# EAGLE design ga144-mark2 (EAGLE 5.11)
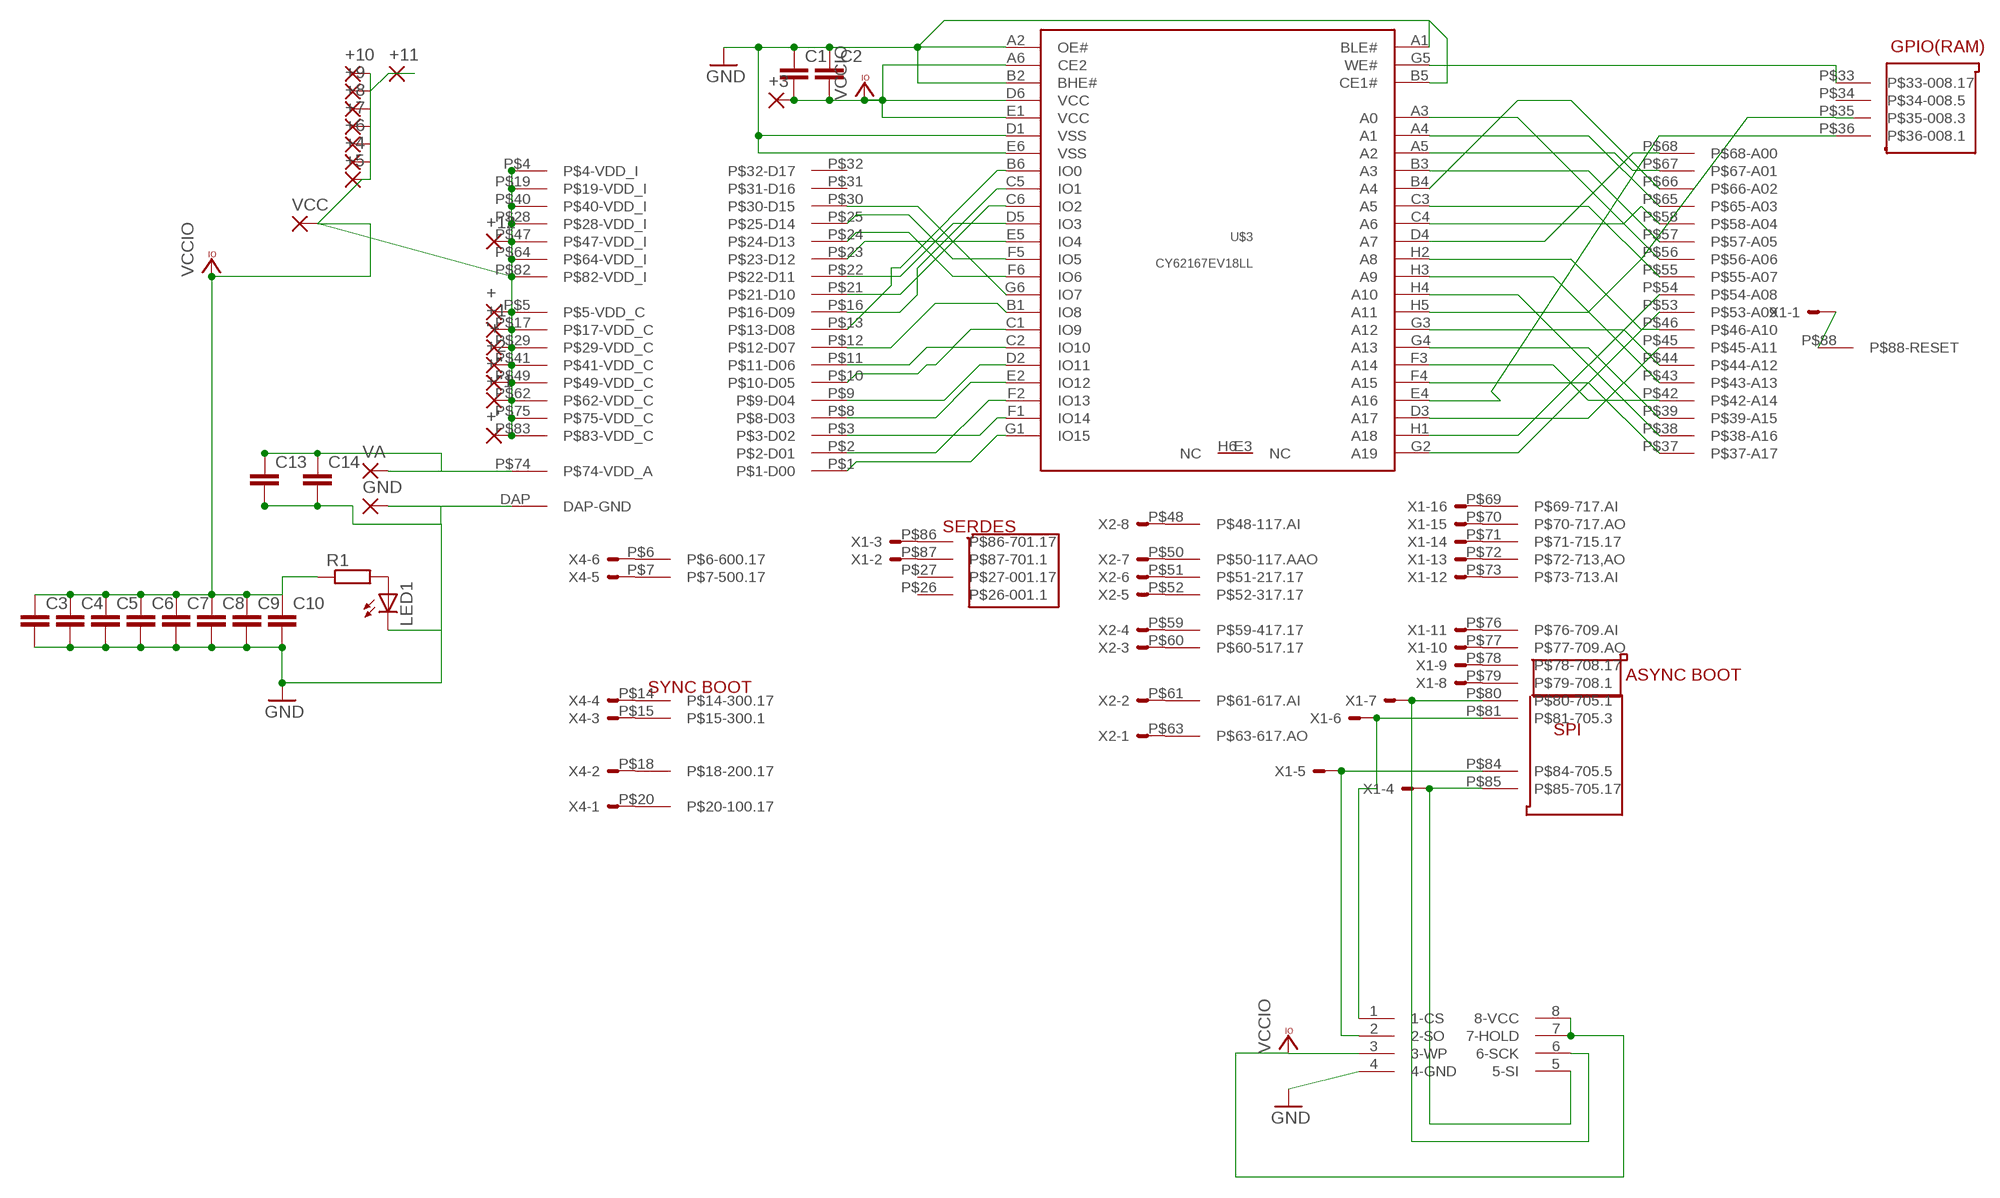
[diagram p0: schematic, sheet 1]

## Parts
'+  1,6/0,8  [1,6/0,8]
+  1,6/0,8  [1,6/0,8]
+1  1,6/0,8  [1,6/0,8]
+2  1,6/0,8  [1,6/0,8]
+3  1,6/0,8  [1,6/0,8]
+4  1,6/0,8  [1,6/0,8]
+5  1,6/0,8  [1,6/0,8]
+6  1,6/0,8  [1,6/0,8]
+7  1,6/0,8  [1,6/0,8]
+8  1,6/0,8  [1,6/0,8]
+9  1,6/0,8  [1,6/0,8]
+10  1,6/0,8  [1,6/0,8]
+11  1,6/0,8  [1,6/0,8]
+12  1,6/0,8  [1,6/0,8]
+"  1,6/0,8  [1,6/0,8]
+"1  1,6/0,8  [1,6/0,8]
+'  1,6/0,8  [1,6/0,8]
C1  C-EUC0805  [C0805]
C2  C-EUC0805  [C0805]
C3  C-EUC0805  [C0805]
C4  C-EUC0805  [C0805]
C5  C-EUC0805  [C0805]
C6  C-EUC0805  [C0805]
C7  C-EUC0805  [C0805]
C8  C-EUC0805  [C0805]
C9  C-EUC0805  [C0805]
C10  C-EUC0805  [C0805]
C13  C-EUC0805  [C0805]
C14  C-EUC0805  [C0805]
GND  2,54/1,0  [2,54/1,0]
LED1  LEDCHIPLED_0805  [CHIPLED_0805]
R1  R-EU_R0805  [R0805]
U$1  GA144A12  [QFN-88]
U$2  AT25DF081-SPI-FLASH  [SOIC8]
U$3  CY62167EV18LL  [BGA48]
VA  WIREPAD2,15/1,0  [2,15/1,0]
VCC  2,54/1,0  [2,54/1,0]
X1  KK-156-16  [KK-156-16]
X2  KK-156-8  [KK-156-8]
X4  KK-156-6  [KK-156-6]

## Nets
GND: C1.1 C2.1 C3.2 C4.2 C5.2 C6.2 C7.2 C8.2 C9.2 C10.2 C13.2 C14.2 GND.1(P) LED1.C U$1.DAP(DAP-GND) U$2.4(4-GND) U$3.A1(BLE#) U$3.A2(OE#) U$3.B2(BHE#) U$3.B5(CE1#) U$3.D1(VSS) U$3.E6(VSS)
N$1: U$1.P$88(P$88-RESET) X1.1
N$2: U$1.P$87(P$87-701.1) X1.2
N$3: C13.1 C14.1 U$1.P$74(P$74-VDD_A) VA.1(P)
N$4: U$1.P$86(P$86-701.17) X1.3
N$5: U$1.P$81(P$81-705.3) U$2.1(1-CS) X1.6
N$6: U$1.P$43(P$43-A13) U$3.H3(A9)
N$7: U$1.P$44(P$44-A12) U$3.G3(A12)
N$8: U$1.P$46(P$46-A10) U$3.H2(A8)
N$9: U$1.P$84(P$84-705.5) U$2.2(2-SO) X1.5
N$10: U$1.P$85(P$85-705.17) U$2.5(5-SI) X1.4
N$11: U$1.P$80(P$80-705.1) U$2.6(6-SCK) X1.7
N$12: U$1.P$79(P$79-708.1) X1.8
N$13: U$1.P$78(P$78-708.17) X1.9
N$14: U$1.P$77(P$77-709.AO) X1.10
N$15: U$1.P$76(P$76-709.AI) X1.11
N$16: U$1.P$73(P$73-713.AI) X1.12
N$17: U$1.P$72(P$72-713,AO) X1.13
N$18: U$1.P$71(P$71-715.17) X1.14
N$19: U$1.P$70(P$70-717.AO) X1.15
N$20: U$1.P$69(P$69-717.AI) X1.16
N$21: U$1.P$63(P$63-617.AO) X2.1
N$22: U$1.P$61(P$61-617.AI) X2.2
N$23: U$1.P$60(P$60-517.17) X2.3
N$24: U$1.P$59(P$59-417.17) X2.4
N$25: U$1.P$52(P$52-317.17) X2.5
N$26: U$1.P$51(P$51-217.17) X2.6
N$27: U$1.P$50(P$50-117.AAO) X2.7
N$28: U$1.P$48(P$48-117.AI) X2.8
N$29: U$1.P$36(P$36-008.1) U$3.E4(A16)
N$30: U$1.P$35(P$35-008.3) U$3.H5(A11)
N$31: U$1.P$55(P$55-A07) U$3.C3(A5)
N$32: U$1.P$57(P$57-A05) U$3.B3(A3)
N$33: U$1.P$56(P$56-A06) U$3.A3(A0)
N$34: U$1.P$58(P$58-A04) U$3.C4(A6)
N$35: U$1.P$6(P$6-600.17) X4.6
N$36: U$1.P$7(P$7-500.17) X4.5
N$37: U$1.P$14(P$14-300.17) X4.4
N$38: U$1.P$15(P$15-300.1) X4.3
N$39: U$1.P$18(P$18-200.17) X4.2
N$40: U$1.P$20(P$20-100.17) X4.1
N$41: U$1.P$53(P$53-A09) U$3.G2(A19)
N$42: U$1.P$54(P$54-A08) U$3.H1(A18)
N$43: U$1.P$39(P$39-A15) U$3.G4(A13)
N$44: U$1.P$45(P$45-A11) U$3.D3(A17)
N$45: U$1.P$38(P$38-A16) U$3.H4(A10)
N$46: U$1.P$42(P$42-A14) U$3.F3(A14)
N$47: U$1.P$65(P$65-A03) U$3.A4(A1)
N$48: U$1.P$37(P$37-A17) U$3.F4(A15)
N$49: U$1.P$66(P$66-A02) U$3.B4(A4)
N$50: U$1.P$67(P$67-A01) U$3.A5(A2)
N$51: U$1.P$68(P$68-A00) U$3.D4(A7)
N$52: U$1.P$30(P$30-D15) U$3.G6(IO7)
N$54: U$1.P$23(P$23-D12) U$3.E5(IO4)
N$55: U$1.P$25(P$25-D14) U$3.F5(IO5)
N$56: U$1.P$12(P$12-D07) U$3.B1(IO8)
N$57: U$1.P$11(P$11-D06) U$3.C2(IO10)
N$58: U$1.P$24(P$24-D13) U$3.F6(IO6)
N$59: U$1.P$22(P$22-D11) U$3.D5(IO3)
N$60: U$1.P$21(P$21-D10) U$3.C6(IO2)
N$61: U$1.P$16(P$16-D09) U$3.C5(IO1)
N$62: U$1.P$13(P$13-D08) U$3.B6(IO0)
N$63: U$1.P$33(P$33-008.17) U$3.G5(WE#)
N$65: U$1.P$10(P$10-D05) U$3.C1(IO9)
N$66: U$1.P$9(P$9-D04) U$3.D2(IO11)
N$67: U$1.P$8(P$8-D03) U$3.E2(IO12)
N$68: U$1.P$3(P$3-D02) U$3.F1(IO14)
N$69: U$1.P$2(P$2-D01) U$3.F2(IO13)
N$70: U$1.P$1(P$1-D00) U$3.G1(IO15)
N$71: LED1.A R1.2
VCCIO: '+.1(P) +1.1(P) +2.1(P) +3.1(P) +4.1(P) +5.1(P) +6.1(P) +7.1(P) +8.1(P) +9.1(P) +10.1(P) +11.1(P) +12.1(P) +"1.1(P) +".1(P) +'.1(P) +.1(P) C1.2 C2.2 C3.1 C4.1 C5.1 C6.1 C7.1 C8.1 C9.1 C10.1 R1.1 U$1.P$4(P$4-VDD_I) U$1.P$5(P$5-VDD_C) U$1.P$17(P$17-VDD_C) U$1.P$19(P$19-VDD_I) U$1.P$28(P$28-VDD_I) U$1.P$29(P$29-VDD_C) U$1.P$40(P$40-VDD_I) U$1.P$41(P$41-VDD_C) U$1.P$47(P$47-VDD_I) U$1.P$49(P$49-VDD_C) U$1.P$62(P$62-VDD_C) U$1.P$64(P$64-VDD_I) U$1.P$75(P$75-VDD_C) U$1.P$82(P$82-VDD_I) U$1.P$83(P$83-VDD_C) U$2.3(3-WP) U$2.7(7-HOLD) U$2.8(8-VCC) U$3.A6(CE2) U$3.D6(VCC) U$3.E1(VCC) VCC.1(P)
Unconnected: U$1.P$26(P$26-001.1) U$1.P$27(P$27-001.17) U$1.P$31(P$31-D16) U$1.P$32(P$32-D17) U$1.P$34(P$34-008.5) U$3.E3(NC) U$3.H6(NC)

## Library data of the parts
'+ + +1-+12 +" +"1 +' = wirepad:1,6/0,8: THROUGH-HOLE PAD
C1-C10 C13 C14 = rcl:C-EU: CAPACITOR, European symbol
GND VCC = wirepad:2,54/1,0: THROUGH-HOLE PAD
LED1 = led:LED: LED
R1 = rcl:R-EU_: RESISTOR, European symbol
U$1 = ga144:GA144A12
U$2 = at25df081-simon:AT25DF081-SPI-FLASH
U$3 = CY62167EV18LL:CY62167EV18LL
VA = wirepad:WIREPAD: Wire PAD connect wire on PCB
X1 = con-molex:KK-156-16: KK 156 HEADER Source: http://www.molex.com/pdm_docs/sd/026604100_sd.pdf; OC_FARNELL: unknown; OC_NEWARK: unknown
X2 = con-molex:KK-156-8: KK 156 HEADER Source: http://www.molex.com/pdm_docs/sd/026604100_sd.pdf; OC_FARNELL: unknown; OC_NEWARK: unknown
X4 = con-molex:KK-156-6: KK 156 HEADER Source: http://www.molex.com/pdm_docs/sd/026604100_sd.pdf; OC_FARNELL: unknown; OC_NEWARK: unknown

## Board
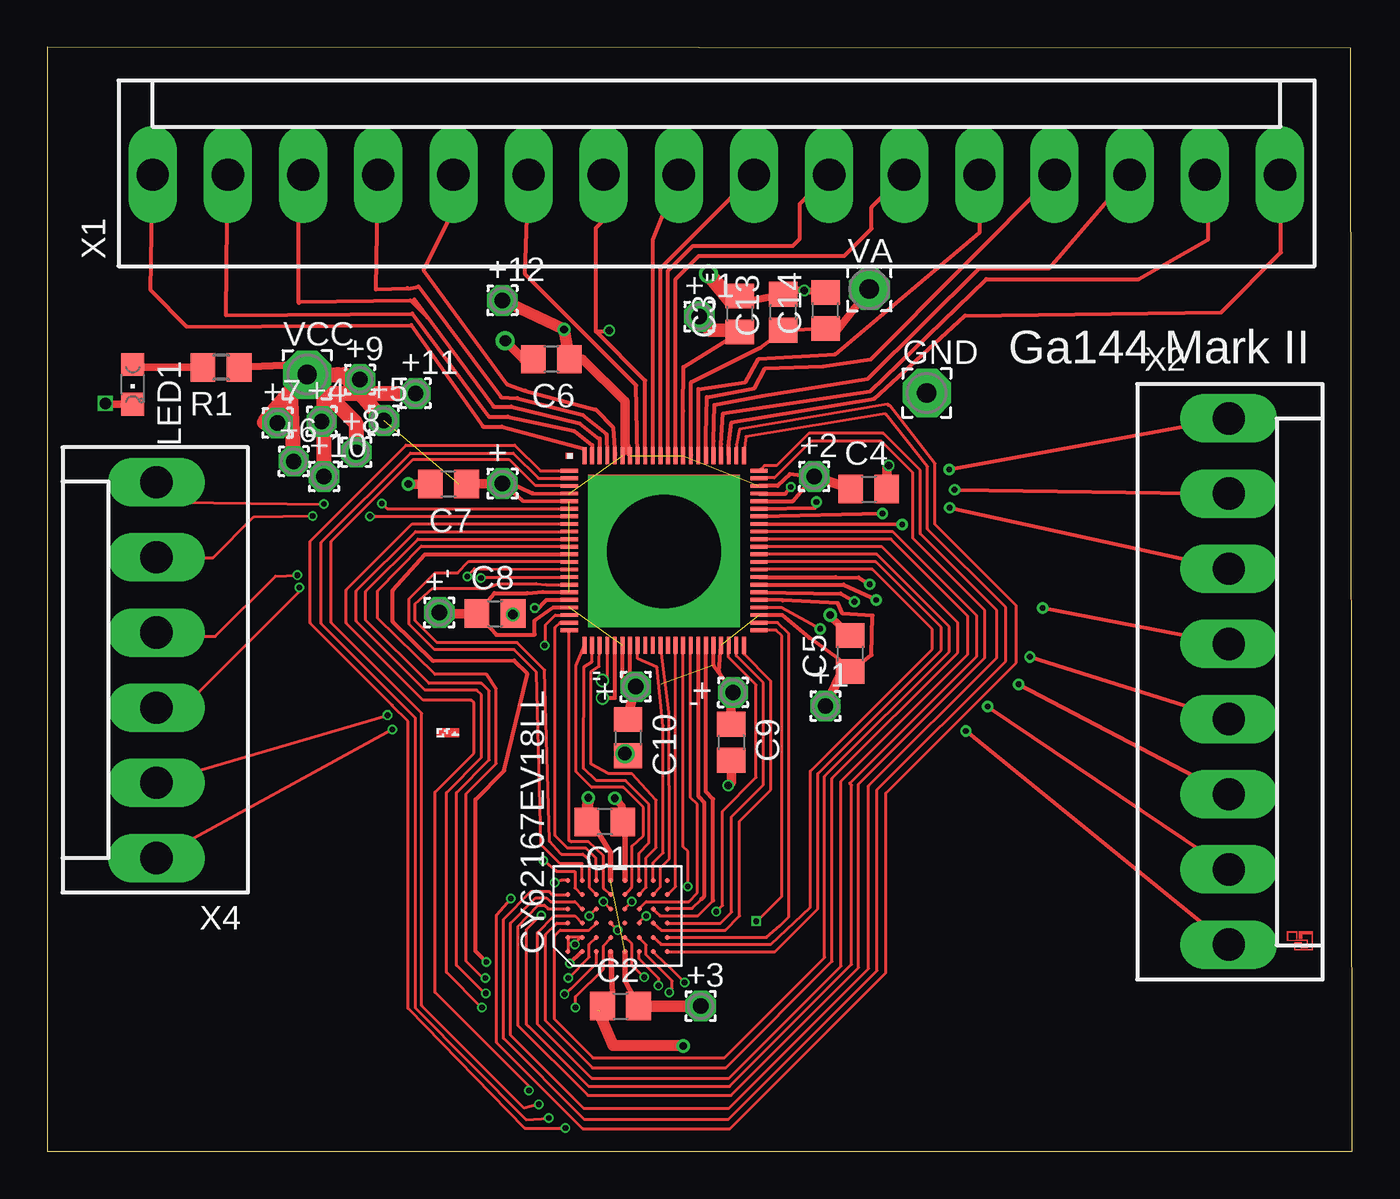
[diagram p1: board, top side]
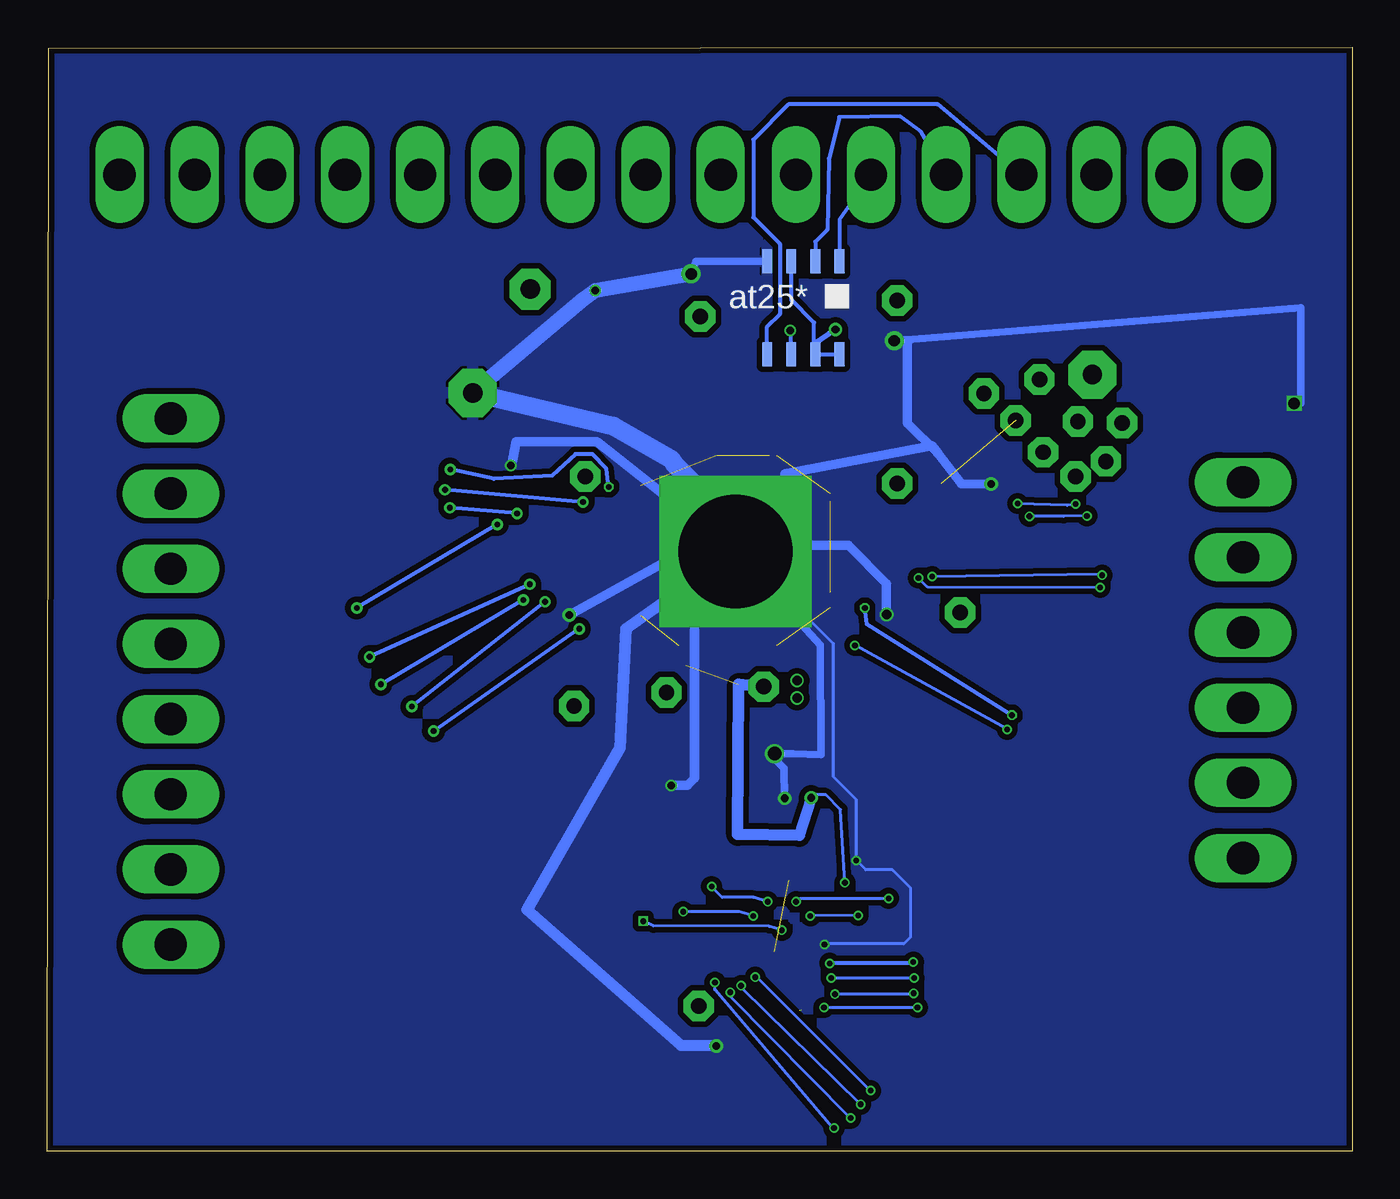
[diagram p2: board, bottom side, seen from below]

Size 68.75 x 58.15 mm. Coordinates in mm from the lower left corner, seen from the top.
Outline: 0,0 68.75,0 68.67,58.1 0,58.15 0,0
Copper layers (1*16): Top 0.035mm / dielectric 1.5mm / Bottom 0.035mm
Design rules "2layer_20110407 *": minimum track width 0.15mm, minimum drill 0.3mm, track to track 0.15mm, track to pad 0.15mm, pad to pad 0.15mm, via to via 0.15mm, smd to smd 0.15mm, copper to edge 0.15mm, drill to drill 0.2mm, minimum pad ring 0.15mm, minimum via ring 0.1mm, stop-mask expansion 0.15mm, vias tented up to drill 0.3mm, thermal gap 0.15mm

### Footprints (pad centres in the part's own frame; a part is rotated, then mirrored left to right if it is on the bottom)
1,6/0,8 = drill 0.813 pad 1.6 octagon: 1 0,0
C0805 = smd 1.3 x 1.5: 1 -0.95,0; 2 0.95,0
2,54/1,0 = drill 1.016 pad 2.54 octagon: 1 0,0
CHIPLED_0805 = smd 1.2 x 1.2: A 0,-1.05; C 0,1.05
R0805 = smd 1.3 x 1.5: 1 -0.95,0; 2 0.95,0
QFN-88 = smd 8 x 8: DAP 5,-5 | smd 0.9 x 0.2: P$1 0,-0.8; P$2 0,-1.2; P$3 0,-1.6; P$4 0,-2; P$5 0,-2.4; P$6 0,-2.8; P$7 0,-3.2; P$8 0,-3.6; P$9 0,-4; P$10 0,-4.4; P$11 0,-4.8; P$12 0,-5.2; P$13 0,-5.6; P$14 0,-6; P$15 0,-6.4; P$16 0,-6.8; P$17 0,-7.2; P$18 0,-7.6; P$19 0,-8; P$20 0,-8.4; P$21 0,-8.8; P$22 0,-9.2; P$45 10,-9.2; P$46 10,-8.8; P$47 10,-8.4; P$48 10,-8; P$49 10,-7.6; P$50 10,-7.2; P$51 10,-6.8; P$52 10,-6.4; P$53 10,-6; P$54 10,-5.6; P$55 10,-5.2; P$56 10,-4.8; P$57 10,-4.4; P$58 10,-4; P$59 10,-3.6; P$60 10,-3.2; P$61 10,-2.8; P$62 10,-2.4; P$63 10,-2; P$64 10,-1.6; P$65 10,-1.2; P$66 10,-0.8 | smd 0.2 x 0.9: P$23 0.8,-10; P$24 1.2,-10; P$25 1.6,-10; P$26 2,-10; P$27 2.4,-10; P$28 2.8,-10; P$29 3.2,-10; P$30 3.6,-10; P$31 4,-10; P$32 4.4,-10; P$33 4.8,-10; P$34 5.2,-10; P$35 5.6,-10; P$36 6,-10; P$37 6.4,-10; P$38 6.8,-10; P$39 7.2,-10; P$40 7.6,-10; P$41 8,-10; P$42 8.4,-10; P$43 8.8,-10; P$44 9.2,-10; P$67 9.2,0; P$68 8.8,0; P$69 8.4,0; P$70 8,0; P$71 7.6,0; P$72 7.2,0; P$73 6.8,0; P$74 6.4,0; P$75 6,0; P$76 5.6,0; P$77 5.2,0; P$78 4.8,0; P$79 4.4,0; P$80 4,0; P$81 3.6,0; P$82 3.2,0; P$83 2.8,0; P$84 2.4,0; P$85 2,0; P$86 1.6,0; P$87 1.2,0; P$88 0.8,0
SOIC8 = smd 0.51 x 1.27: 1 2.04,2.49; 2 0.77,2.49; 3 -0.5,2.49; 4 -1.77,2.49; 5 -1.77,-2.41; 6 -0.5,-2.41; 7 0.77,-2.41; 8 2.04,-2.41
BGA48 = smd 0.26 x 0.26: A1 -1.875,2.625; A2 -1.125,2.625; A3 -0.375,2.625; A4 0.375,2.625; A5 1.125,2.625; A6 1.875,2.625; B1 -1.875,1.875; B2 -1.125,1.875; B3 -0.375,1.875; B4 0.375,1.875; B5 1.125,1.875; B6 1.875,1.875; C1 -1.875,1.125; C2 -1.125,1.125; C3 -0.375,1.125; C4 0.375,1.125; C5 1.125,1.125; C6 1.875,1.125; D1 -1.875,0.375; D2 -1.125,0.375; D3 -0.375,0.375; D4 0.375,0.375; D5 1.125,0.375; D6 1.875,0.375; E1 -1.875,-0.375; E2 -1.125,-0.375; E3 -0.375,-0.375; E4 0.375,-0.375; E5 1.125,-0.375; E6 1.875,-0.375; F1 -1.875,-1.125; F2 -1.125,-1.125; F3 -0.375,-1.125; F4 0.375,-1.125; F5 1.125,-1.125; F6 1.875,-1.125; G1 -1.875,-1.875; G2 -1.125,-1.875; G3 -0.375,-1.875; G4 0.375,-1.875; G5 1.125,-1.875; G6 1.875,-1.875; H1 -1.875,-2.625; H2 -1.125,-2.625; H3 -0.375,-2.625; H4 0.375,-2.625; H5 1.125,-2.625; H6 1.875,-2.625
2,15/1,0 = drill 1.016 pad 2.159 octagon: 1 0,0
KK-156-16 = drill 1.7 pad 2.184 long: 1 -29.7,0; 2 -25.74,0; 3 -21.78,0; 4 -17.82,0; 5 -13.86,0; 6 -9.9,0; 7 -5.94,0; 8 -1.98,0; 9 1.98,0; 10 5.94,0; 11 9.9,0; 12 13.86,0; 13 17.82,0; 14 21.78,0; 15 25.74,0; 16 29.7,0
KK-156-8 = drill 1.7 pad 2.184 long: 1 -13.86,0; 2 -9.9,0; 3 -5.94,0; 4 -1.98,0; 5 1.98,0; 6 5.94,0; 7 9.9,0; 8 13.86,0
KK-156-6 = drill 1.7 pad 2.184 long: 1 -9.9,0; 2 -5.94,0; 3 -1.98,0; 4 1.98,0; 5 5.94,0; 6 9.9,0

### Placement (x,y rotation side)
'+  36.12,24.18 90 top
+  23.98,35.17 0 top
+1  41,23.45 0 top
+2  40.4,35.55 0 top
+3  34.42,7.65 0 top
+4  14.45,38.45 0 top
+5  17.73,38.5 0 top
+6  12.98,36.35 0 top
+7  12.12,38.38 0 top
+8  16.27,36.83 0 top
+9  16.48,40.65 0 top
+10  14.57,35.55 0 top
+11  19.4,39.92 0 top
+12  23.98,44.83 0 top
+"  31,24.47 90 top
+"1  34.35,43.97 0 top
+'  20.65,28.37 0 top
C1  29.38,17.35 180 top
C2  30.2,7.65 0 top
C3  36.49,44.11 90 top
C4  43.28,34.89 0 top
C5  42.31,26.22 90 top
C6  26.55,41.72 180 top
C7  21.14,35.14 180 top
C8  23.59,28.32 0 top
C9  36.03,21.55 270 top
C10  30.59,21.79 270 top
C13  38.77,44.2 90 top
C14  41,44.3 90 top
GND  46.34,39.95 0 top
LED1  4.5,40.4 180 top
R1  9.15,41.3 180 top
U$1  27.5,36.65 0 top
U$2  29.05,44.4 0 bottom
U$3  30.05,12.4 90 top
VA  43.31,45.42 0 top
VCC  13.69,40.92 0 top
X1  35.25,51.45 0 top
X2  62.25,24.75 270 top
X4  5.75,25.35 90 top

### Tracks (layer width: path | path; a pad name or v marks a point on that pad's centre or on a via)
GND  (via drill 0.3 pad 0.5, 0.4 pad 0.5, 0.4 pad 0.6, 0.4 pad 0.7, 0.5 pad 0.5, 0.6, 0.6 pad 1, 0.7 pad 1, 6 pad 8)  (1 unrouted)
  Top 0.15: U$3.A1 U$3.A2 U$3.B2 28.08,11.27 27.8,10.93 27.45,10.9 v27.8,10.9 | U$3.B5 28.15,13.52 27.8,13.88 27.8,14.75 26.82,14.75 v26.12,15.32 | U$3.E6 30.42,17.6 30.3,17.72 30.3,17.7 30.27,17.68 30.27,18.18
  Top 0.2: v32.5,31.6 U$1.DAP | C2.1 29.12,7.4 | 30.42,16.53 C1.1 | v41.25,28.25 41.2,28.22
  Top 0.3: U$3.E6 30.42,16.53 | 29.02,7.43 29.77,8.27 U$3.D1
  Top 0.4: 41.2,28.22 C5.2 | C10.2 30.53,20.84 v30.42,20.95 | v29.9,18.6 30.27,18.18 | C14.2 39.27,45.38 v39.88,45.35 | C3.2 36.19,44.61 C13.2
  Top 0.406: 3.05,39.35 LED1.C | 3.05,39.35 3,39.35 | v3.05,39.4 3.05,39.35
  Top 0.5: C7.2 v19.03,35.14 v19.02,35.15 | C4.2 44.23,36.03 v44.33,36.12 | C9.2 36.03,19.43 v35.88,19.28 | C8.2 24.54,28.29 v24.52,28.28 | C6.2 25.1,41.72 v24.12,42.7
  Top 0.6: v33.5,5.55 29.8,5.57 29.02,7.43
  Top 0.8: C3.2 35.99,44.84 v34.83,46.22
  Bottom 0.15: v26.12,15.32 26.12,15.43 | v26.12,15.32 26.12,18.53 27.32,19.72 27.32,26.75 31.86,31.29 | v27.8,10.9 27.75,10.93 23.62,10.93 23.25,11.3 23.25,13.85 24.23,14.82 25.62,14.82 v26.12,15.32 | C10.2 30.53,20.84 v30.42,20.95
  Bottom 0.2: v32.5,31.6 33.47,33.41 33.67,33.8 34.1,34.6 | 35.75,36.25 35.85,36.42
  Bottom 0.4: v30.42,20.95 29.48,20.95 27.98,20.9 28.02,26.65 v32.5,31.6 | v29.9,18.6 29.92,20.17 C10.2 | U$2.4 34.56,46.89 v34.83,46.22
  Bottom 0.406: v3.05,39.4 2.7,39.4 2.7,44.45 v24.12,42.7
  Bottom 0.5: 33.47,33.41 U$1.DAP | 33.67,33.8 35.8,32.95 | v32.5,31.6 31.86,31.29 29.45,30.1 | v32.5,31.6 32.83,31.23 | 32.83,31.23 35.4,28.4 | 21.83,36.77 22.15,37.17 29.88,35.7 29.87,34.2 32.83,31.23 | 21.83,36.77 20.57,35.17 v19.02,35.15 | v41.25,28.25 35.95,31.2 32.9,31.2 v32.5,31.6 | v44.33,36.12 44.3,36.12 44.05,37.38 39.77,37.38 v32.5,31.6 | v35.88,19.28 35.02,19.28 34.65,19.65 34.65,29.45 v32.5,31.6 | v24.52,28.28 24.52,29.9 26.55,31.93 32.17,31.93 v32.5,31.6 | v24.12,42.7 23.55,42.7 23.43,42.58 23.43,38.36 21.83,36.77
  Bottom 0.6: v33.5,5.55 35.38,5.57 43.48,12.72 38.58,21.25 38.25,27.53 v32.5,31.6
  Bottom 0.8: v34.83,46.22 v39.88,45.35 40.47,44.92 GND.1
  Bottom 1: 34.1,34.6 35.75,36.25 | 35.85,36.42 38.92,38.2 GND.1
  pour Bottom (isolate 0.3): 0.45,57.83 0.4,0.35 68.17,0.25 68.15,57.6 0.58,57.7
N$1
  Top 0.2: U$1.P$88 28.3,37 23.95,38.17 22.95,38.17 19.18,43.53 7.35,43.45 5.45,45.35 X1.1
N$2
  Top 0.2: X1.2 9.41,44.06 9.4,44.05 19.23,44.12 23.25,38.7 24.25,38.7 27.75,37.95 28.7,37.2 U$1.P$87
N$3
  Top 0.2: C14.1 C13.1 37.55,42.33 33.92,40.53 33.92,36.67 U$1.P$74
  Top 0.4: C14.1 41.41,43 VA.1
N$4
  Top 0.2: 29.1,37.5 U$1.P$86 | 29.1,37.5 29.1,37.55 | 29.1,37.5 28.05,38.35 24.45,39.22 23.5,39.22 19.32,44.88 20.02,43.92 19.12,44.83 13.3,44.75 13.25,44.7 13.25,49.18 X1.3
N$5
  Top 0.2: X1.6 25.18,46.2 31.02,40.35 U$1.P$81
  Bottom 0.2: U$2.1 27.01,49.09 X1.6
N$6
  Top 0.15: U$3.H3 35.48,12.02 36.05,12.6 36.05,17.62 37.73,19.3 37.73,24.68 36.3,26.1 U$1.P$43 36.33,26.62
N$7
  Top 0.15: U$3.G3 32.33,11.65 35.73,11.65 36.48,12.4 36.48,17.4 38.12,19.05 38.12,24.78 36.7,26.2 U$1.P$44
N$8
  Top 0.15: U$3.H2 37.9,11.27 38.6,11.88 39.08,12.35 39.08,27.28 38.48,27.85 U$1.P$46
N$9
  Top 0.2: U$1.P$84 29.8,38.15 28.9,39.08 25.18,40.08 24.23,40.4 19.82,46.42 21.25,49.26 X1.5
  Bottom 0.2: U$2.2 28.28,47.92 27.65,48.55 27.58,52.3 27.02,54.48 23.82,54.53 22.73,53.71 X1.5
N$10
  Top 0.2: X1.4 17.33,45.43 17.3,45.4 18.98,45.47 19,45.45 19.55,45.55 23.9,39.72 24.75,39.67 28.2,38.8 29.45,37.8 29.45,37.75 U$1.P$85
  Bottom 0.2: X1.4 21.83,55.15 29.7,55.15 31.55,53.3 31.55,49.2 30.15,47.8 30.15,44.1 30.85,43.4 30.85,42.02 U$2.5
N$11  (via drill 0.4)
  Top 0.2: U$1.P$80 31.5,40.6 28.9,43.2 | 28.9,43.2 28.9,48.65 29.25,49 29.25,49.26 X1.7 | 28.9,43.2 29.55,43.2 v29.6,43.25
  Bottom 0.2: v29.6,43.25 29.6,42.04 U$2.6
N$12
  Top 0.2: U$1.P$79 31.9,48.03 X1.8
N$13
  Top 0.2: U$1.P$78 32.3,46.52 X1.9
N$14
  Top 0.2: U$1.P$77 32.7,46.38 34.02,47.7 39.27,47.7 39.65,48.08 39.65,49.91 X1.10
N$15
  Top 0.2: U$1.P$76 33.1,45.95 34.33,47.17 42,47.17 43.42,48.6 43.42,49.73 X1.11
N$16
  Top 0.2: U$1.P$73 34.3,40.15 36.77,40.53 37.48,41.75 41.52,42 49.12,48.42 49.12,50.73 X1.12
N$17
  Top 0.2: U$1.P$72 34.7,37.72 34.75,39.72 37.25,40.2 37.83,41.25 40.88,41.35 43.4,41.72 X1.13
N$18
  Top 0.2: U$1.P$71 35.1,37.42 35.15,39.33 37.67,39.8 43.25,40.7 49.1,46.53 52.8,46.53 X1.14
N$19
  Top 0.2: U$1.P$70 35.5,37.25 35.6,38.88 43.38,40.05 49.48,45.95 57.52,45.95 61.17,48.03 61.17,49.36 X1.15
N$20
  Top 0.2: U$1.P$69 35.9,37.17 36.05,38.4 43.58,39.65 48.35,44.03 61.85,44.2 65,47.35 65,51.4 X1.16
N$21  (via drill 0.3, 0.3 pad 0.6)
  Top 0.2: U$1.P$63 38.9,34.65 v39.17,35 | v47.52,35.92 X2.1
  Bottom 0.2: v39.17,35 39.3,35.95 40.02,36.72 40.92,36.72 42.15,35.6 45.23,35.42 v47.52,35.92
N$22  (via drill 0.3 pad 0.6)
  Top 0.2: U$1.P$61 40.42,33.9 v40.52,34.2 | v47.8,34.85 X2.2
  Bottom 0.2: v40.52,34.2 v47.8,34.85
N$23  (via drill 0.3 pad 0.6)
  Top 0.2: U$1.P$60 v44,33.6 | v47.55,33.9 X2.3
  Bottom 0.2: v44,33.6 v47.55,33.9
N$24  (via drill 0.3 pad 0.6)
  Top 0.2: U$1.P$59 v45.05,33.03 | v52.45,28.62 X2.4
  Bottom 0.2: v45.05,33.03 v52.45,28.62
N$25  (via drill 0.3 pad 0.6)
  Top 0.2: U$1.P$52 41.55,30.25 42.75,30.22 v43.33,29.87 | v51.77,26.05 X2.5
  Bottom 0.2: v43.33,29.87 v51.77,26.05
N$26  (via drill 0.3 pad 0.6)
  Top 0.2: U$1.P$51 41.95,29.85 v43.67,29.05 | v51.17,24.6 X2.6
  Bottom 0.2: v43.67,29.05 v51.17,24.6
N$27  (via drill 0.3 pad 0.6)
  Top 0.2: U$1.P$50 41.8,29.37 v42.52,28.95 | v49.55,23.43 X2.7
  Bottom 0.2: v42.52,28.95 v49.55,23.43
N$28  (via drill 0.3 pad 0.6)
  Top 0.15: U$1.P$48 38.67,28.65 v40.73,27.53
  Top 0.2: v48.4,22.15 X2.8
  Bottom 0.2: v40.73,27.53 48.35,22.15 v48.4,22.15
N$29  (via drill 0.3)
  Top 0.15: U$3.E4 30.42,12.8 v30.8,13.15 | v33.75,13.95 33.75,15.8 33.5,16.05 U$1.P$36
  Bottom 0.15: v30.8,13.15 31.55,13.38 33.2,13.38 v33.75,13.95
N$30
  Top 0.15: U$1.P$35 33.1,13.95 U$3.H5
N$31
  Top 0.15: U$3.C3 28.55,11.65 27.02,11.65 26.73,11.35 26.73,6.95 28.75,4.93 35.67,4.93 40.96,10.21 40.95,10.22 40.95,19.75 47.52,26.32 47.52,27.62 43.7,31.45 U$1.P$55
N$32
  Top 0.15: U$3.B3 27.8,12.4 26.7,12.4 25.82,11.52 25.82,6.7 28.67,3.85 35.92,3.85 41.83,9.75 41.83,19.5 48.5,26.18 48.5,28.2 44.45,32.25 U$1.P$57
N$33
  Top 0.15: U$3.A3 26.85,12.02 26.25,11.43 26.25,6.88 28.73,4.4 35.75,4.4 41.35,10 41.35,19.65 47.98,26.28 47.98,27.85 43.98,31.85 U$1.P$56
N$34  (via drill 0.3 pad 0.5)
  Top 0.15: U$3.C4 28.9,12.77 v28.55,12.4 | v26.02,12.43 25.98,12.43 25.25,11.7 25.25,6.68 25.35,6.57 25.38,6.57 28.52,3.43 35.95,3.43 42.38,9.85 42.38,19.3 42.27,19.4 42.3,19.4 48.98,26.07 48.98,28.22 44.55,32.65 U$1.P$58
  Bottom 0.15: v26.02,12.43 v28.55,12.4
N$35  (via drill 0.3 pad 0.5)
  Top 0.15: U$1.P$6 17.9,33.85 v17.62,34.12 | v14.57,34.1 6.8,34.2 X4.6
  Bottom 0.15: v17.62,34.12 15.02,34.03 v14.57,34.1
N$36  (via drill 0.3 pad 0.5)
  Top 0.15: v17,33.45 U$1.P$7 | v13.98,33.47 10.88,33.42 8.72,31.28 5.77,31.28 X4.5
  Bottom 0.15: v17,33.45 15.2,33.45 v13.98,33.47
N$37  (via drill 0.3 pad 0.5)
  Top 0.15: U$1.P$14 22.5,30.7 v22.12,30.28 | v13.18,30.35 12.02,30.3 8.85,27.12 5.96,27.12 X4.4
  Bottom 0.15: v22.12,30.28 13.27,30.4 v13.18,30.35
N$38  (via drill 0.3 pad 0.5)
  Top 0.15: U$1.P$15 22.98,30.25 v22.85,30.2 | v13.27,29.7 13.45,29.68 7.15,23.37 X4.3
  Bottom 0.15: v22.85,30.2 22.38,29.72 v13.27,29.7
N$39  (via drill 0.3)
  Top 0.15: X4.2 v17.93,22.97
  Top 0.2: v25.68,28.62 25.75,28.47 26.3,29.05 U$1.P$18
  Bottom 0.2: v17.93,22.97 25.57,27.78 v25.68,28.62
N$40  (via drill 0.3 pad 0.5)
  Top 0.15: U$1.P$20 26.75,28.25 26.25,27.75 26.25,26.7 v26.2,26.65 | X4.1 v18.18,22.22
  Bottom 0.15: v18.18,22.22 v26.2,26.65
N$41
  Top 0.15: U$1.P$53 43.48,30.65 46.62,27.5 46.62,26.45 40.2,20.03 40.2,12.85 38.12,10.9 32.33,10.9 U$3.G2
N$42
  Top 0.15: U$1.P$54 43.65,31.05 47.1,27.6 47.1,26.4 40.6,19.9 40.6,12.77 38.35,10.52 U$3.H1
N$43
  Top 0.15: 35.08,13.2 34.27,12.4 32.27,12.4 31.92,12.72 U$3.G4
  Top 0.2: U$1.P$39 34.7,18.95 35.08,18.55 35.08,13.2
N$44  (via drill 0.3 pad 0.5)
  Top 0.15: U$3.D3 v30.05,11.65 | U$1.P$45 38.4,27.45 38.7,27.15 38.7,13.43 37.4,12.12 v37.35,12.12
  Bottom 0.15: v30.05,11.65 30.73,11.85 36.83,11.88 v37.35,12.12
N$45
  Top 0.15: U$3.H4 32.7,12.8 33.98,12.8 34.46,13.29
  Top 0.2: U$1.P$38 34.3,18.72 34.35,18.65 34.62,18.37 34.62,13.45 34.46,13.29
N$46  (via drill 0.3 pad 0.5)
  Top 0.15: U$1.P$42 35.9,26.03 37.35,24.57 37.35,19.7 35.58,17.93 35.58,12.95 v35.25,12.62 | U$3.F3 31.17,12.07 v31.55,12.4
  Bottom 0.15: v31.55,12.4 32.3,12.62 v35.25,12.62
N$47
  Top 0.15: U$3.A4 26.38,12.77 26.18,12.97 25.85,12.97 24.8,11.85 24.8,6.62 28.48,2.95 36.02,2.95 42.75,9.68 42.75,19.35 49.4,26 49.4,28.5 45.6,32.3 45.6,35.75 43.95,37.4 40.23,37.4 38.3,35.47 37.52,35.47 U$1.P$65
N$48
  Top 0.15: U$3.F4 31.55,13.15 33.8,13.15 34.25,13.62 34.25,18.28 33.9,18.62 U$1.P$37
N$49
  Top 0.15: U$3.B4 28.15,12.77 27.8,13.15 26.52,13.15 26.3,13.35 25.73,13.35 24.4,12.02 24.4,6.12 28.25,2.27 35.92,2.27 43.27,9.62 43.27,19.25 50.02,26 50.02,28.5 46,32.53 46,35.88 44.05,37.83 40.12,37.83 38.42,36.12 37.77,36.12 U$1.P$66
N$50
  Top 0.15: U$3.A5 26.6,13.52 26.45,13.7 25.48,13.7 24.02,12.22 24.02,5.95 28.27,1.7 35.9,1.7 43.73,9.52 43.73,19.05 50.5,25.82 50.5,28.65 46.38,32.78 46.38,36.08 44.15,38.85 36.8,37.65 36.7,36.88 U$1.P$67
N$51  (via drill 0.3 pad 0.5)
  Top 0.15: U$1.P$68 36.3,37.22 36.48,38.05 44.27,39.35 44.39,39.29 | U$3.D4 29.65,12.77 v29.3,13.15 | v24.43,13.32 23.68,12.45 23.68,5.72 28.2,1.2 35.98,1.2 44.17,9.4 44.17,18.87 51.05,25.75 51.05,28.75 46.77,33.03 46.77,36.22 44.39,39.29 | 44.39,39.29 44.3,39.3
  Bottom 0.15: v29.3,13.15 29.1,13.3 24.57,13.3 v24.43,13.32
N$52
  Top 0.15: U$1.P$30 31.12,26.62 31.1,25.95 32.12,25.5 32.45,22.4 32.45,15.72 31.92,15.2 U$3.G6
N$53  (via drill 0.5 pad 0.5)
  other vias: 29.25,23.87
N$54
  Top 0.15: U$3.E5 30.8,13.95 30.8,16.07 31.4,16.62 31.4,18.12 30.35,19.18 28.67,19.18 27.85,20 27.85,25.57 U$1.P$23
N$55
  Top 0.15: U$3.F5 31.55,13.9 31.55,15.47 32.08,16 32.08,18.5 30.8,19.9 29.58,19.9 28.65,20.4 28.65,25.28 29.08,25.55 U$1.P$25
N$56  (via drill 0.3 pad 0.5)
  Top 0.2: U$3.B1 28.15,10.52 v27.52,9.9 | v23.12,9.97 22.55,10.55 22.55,18.53 24.07,20.05 25.3,25.15 24.6,25.85 20.32,25.82 18.2,27.9 18.2,29.55 19.9,31.45 U$1.P$12
  Bottom 0.2: v27.52,9.9 23.2,9.9 v23.12,9.97
N$57  (via drill 0.3 pad 0.5)
  Top 0.15: U$3.C2 28.55,10.9 28.55,10.22 v27.45,9.12 | v23.07,9.12 22.95,9.12 22.05,10.02 22.05,18.82 23.65,20.43 23.65,24.37 23.15,25.12 20.43,25.12 17.4,28.07 17.4,29.53 19.7,31.87 27.45,31.87 U$1.P$11
  Bottom 0.15: v23.07,9.12 v27.45,9.12
N$58
  Top 0.15: U$3.F6 31.17,15.7 31.7,16.25 31.7,18.28 30.48,19.53 28.92,19.53 28.25,20.18 28.27,25.53 28.7,25.8 U$1.P$24
N$59
  Top 0.15: U$3.D5 29.33,13.82 29.3,13.88 29.3,15.57 28.52,16.3 27.6,16.3 27.5,16.35 U$1.P$22
N$60
  Top 0.15: U$3.C6 28.9,15.45 28.38,15.97 27.4,15.97 26.75,16.62 26.75,27.6 27,27.85 U$1.P$21
N$61
  Top 0.15: U$3.C5 28.55,13.9 28.55,15.35 28.2,15.65 27.07,15.65 26.45,16.32 26.2,25.35 24.75,26.8 20.52,26.8 19.38,27.95 19.38,28.85 20.3,29.65 23.1,29.68 23.75,29.9 25.77,29.9 26.27,29.85 U$1.P$16
N$62
  Top 0.15: U$3.B6 28.17,15.15 27.02,15.15 26.02,16.15 25.77,25.25 24.6,26.43 20.4,26.43 19.05,27.78 19.05,29.1 20.43,30.47 21.62,30.47 22.2,31.07 27.48,31.07 U$1.P$13
N$63
  Top 0.15: U$1.P$33 32.75,23.12 32.77,15.43 32.3,14.95 32.3,13.93 U$3.G5
N$64  (via drill 0.5 pad 0.5)
  other vias: 29.25,24.8
N$65  (via drill 0.3 pad 0.5)
  Top 0.15: U$3.C1 28.92,9.9 27.58,8.55 27.55,8.55 27.4,8.4 27.38,8.4 v27.25,8.27 | v23.1,8.32 23.02,8.32 21.55,9.8 21.55,18.9 23.27,20.62 23.27,24.25 22.88,24.65 20.1,24.65 16.77,27.97 16.77,29.5 19.52,32.25 U$1.P$10
  Bottom 0.15: v27.25,8.27 23.15,8.27 v23.1,8.32
N$66  (via drill 0.3 pad 0.5)
  Top 0.15: U$3.D2 29.67,11.22 29.3,10.82 29.3,9.6 27.83,8.15 v27.83,7.57 | v22.9,7.57 22.88,7.57 21.02,9.43 21.02,18.9 22.88,20.75 22.88,24.05 22.62,24.3 19.9,24.3 16.27,27.93 16.27,29.53 19.4,32.65 U$1.P$9
  Bottom 0.15: v22.9,7.57 v27.83,7.57
N$67  (via drill 0.3 pad 0.5)
  Top 0.15: U$3.E2 30.45,11.27 30.8,10.93 30.8,9.75 30.9,9.65 30.98,9.65 v31.45,9.18 | v25.38,3.2 25.48,3.32 20.43,8.38 20.43,18.93 22.48,20.97 22.48,23.65 22.35,23.78 19.8,23.78 15.75,27.82 15.75,29.57 19.23,33.05 U$1.P$8
  Bottom 0.15: v31.45,9.18 31.35,9.18 v25.38,3.2
N$68  (via drill 0.3 pad 0.5)
  Top 0.15: U$3.F1 31.17,10.15 32.23,9.1 32.23,8.75 v32.2,8.72 | v25.9,2.47 25.12,2.27 19.73,7.68 19.73,23.07 14.95,27.85 14.95,32.12 19.27,36.45 24.32,36.45 25.7,35.08 27.48,35.08 U$1.P$3
  Bottom 0.15: v32.2,8.72 32.15,8.6 v25.9,2.47
N$69  (via drill 0.3 pad 0.5)
  Top 0.15: U$3.F2 31.17,11.25 31.55,10.88 31.55,10.35 32.92,8.97 32.92,8.57 v32.77,8.38 | v26.43,1.75 25.23,1.68 19.4,7.55 19.4,22.82 14.43,27.8 14.43,32.08 19.12,36.78 24.55,36.78 25.88,35.45 U$1.P$2
  Bottom 0.15: v32.77,8.38 32.73,8.12 v26.43,1.75
N$70  (via drill 0.3 pad 0.5)
  Top 0.15: U$1.P$1 25.98,35.85 24.62,37.2 18.9,37.2 13.85,32.15 13.85,27.82 18.18,23.5 18.18,23.47 19,22.65 19,7.52 25.15,1.22 v27.3,1.22 | U$3.G1 32.62,9.82 32.65,9.82 v33.58,8.9
  Bottom 0.15: v33.58,8.9 33.58,8.5 27.38,1.25 27.25,1.3 v27.3,1.22
N$71
  Top 0.406: R1.2 4.5,41.3 LED1.A
VCCIO  (via drill 0.3 pad 0.5, 0.4 pad 0.7)  (9 unrouted)
  Top 0.15: U$3.A6 27.1,14.27 v26.73,14.15
  Top 0.2: C1.2 28.67,17.35 | U$1.P$19 26.65,28.65 25.68,27.97 25.68,27.22 23.66,27.2 C8.1 23.56,29.4 25.3,29.4 26.1,29.47 U$1.P$17 | U$1.P$5 25.02,34.28 24,35.2 +.1 23.57,35.62 25.55,34.67 U$1.P$4 | U$1.P$28 30.3,24.72 +".1 30.7,24.62 U$1.P$29 | U$1.P$41 35.4,25.28 '+.1 35.1,25.6 U$1.P$40 | U$1.P$47 38.73,28.25 40.15,27.05 42.02,25.68 C5.1 43.42,26.15 43.48,28.22 41.9,28.32 41.65,28.87 38.75,29.03 U$1.P$49 | U$1.P$62 39.27,34.25 +2.1 40.8,35.45 39.12,35.67 38.48,35.05 U$1.P$64 | U$3.E1 30.4,9 | 30.5,36.85 30.5,37.15 | U$1.P$83 30.5,36.85 | 30.5,36.85 U$1.P$82 | C3.1 33.52,41.31 33.5,39 U$1.P$75
  Top 0.3: U$3.D6 29.67,15.72 28.67,17.35 | U$3.E1 30.42,8.97 C2.2
  Top 0.406: R1.1 13.69,41.45 VCC.1
  Top 0.5: C8.1 20.7,28.32 +'.1 | +.1 21.66,35.17 C7.1 | +".1 30.55,22.79 C10.1 | C9.1 35.98,24.14 '+.1 | C5.1 42.02,25.6 +1.1 | +2.1 42.31,34.9 C4.1 | C6.1 28.2,41.72 30.42,39.5 30.42,37.22 30.5,37.15
  Top 0.6: v28.5,18.62 C1.2 | C2.2 +3.1 | +12.1 v27.23,43.3 C6.1
  Top 0.7: +"1.1 34.35,43.83 34.92,43.25 36.4,43.25 C3.1
  Top 0.8: VCC.1 15.32,40.92 | 15.32,40.92 +9.1 | 15.32,40.92 15.64,40.92 +5.1 | +8.1 16.25,38.35 VCC.1 | +4.1 14.7,39.91 VCC.1 | 12.8,40.03 +6.1 | VCC.1 12.8,40.03 | +7.1 12.12,38.47 12.07,38.22 11.43,38.4 12.8,40.03 | +10.1 14.57,40.03 VCC.1 | +11.1 14.68,39.92 VCC.1
  Bottom 0.15: v26.73,14.15 26.95,18 27.73,18.78 28.35,18.78 v28.5,18.62
  Bottom 0.2: U$2.3 29.55,44.85 28.35,43.65 28.35,42.61 28.34,42.55 U$2.7 U$2.8
  Bottom 0.3: v27.23,43.3 28.34,42.55
  Bottom 0.6: v28.5,18.62 29.12,16.65 32.38,16.7 32.33,24.6 +".1
(copper drawn outside any net)
  shapes: Top area x37

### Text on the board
tNames: Ga144 Mark II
